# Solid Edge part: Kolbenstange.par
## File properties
Username: bmolnar
Dokumentum tartalom típus: 0
Author: bmolnar
Last saved by: bmolnar
Revision: 82
Sűrűség: 0,000 kg/m^3
Pontosság: 0,990
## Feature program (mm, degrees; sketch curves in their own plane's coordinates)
base feature "unnamed BaseFeature 1"
sketch for "unnamed Protrusion 1" plane through (-0.0012, 0, -18.75) normal (0, 0, -1) x-axis (0, -1, 0)
  circle centre (0, -0.0012) radius 25
extrude "unnamed Protrusion 1" add finite 8.3 along +normal
sketch for "Kihúzás_2" #1 plane through (-0.0012, 0, -18.75) normal (0, 0, -1) x-axis (0, -1, 0)
  circle centre (0, -0.0012) radius 8
sketch for "Kihúzás_2" #2 plane through (-0.0012, 0, -18.75) normal (0, 0, -1) x-axis (0, -1, 0)
  circle centre (0, -0.0012) radius 25
extrude "Kihúzás_2" add finite 18.8 along -normal
sketch for "Furat_1" plane through (0, 0, 31.0163) normal (0, 0, 1) x-axis (0, 1, 0)
  hole centre (0, 0) bore radius 3.3235
hole "Furat_1" nominal diameter 8 finite  VBottomAngle = 118 deg; ThreadDepth = 14.27 mm
chamfer "Letörés_1" setback 0.7  SetBackValue2 = 45 deg
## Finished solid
Body 1: solid body, 17 faces, 23 edges, 8 vertices.
  Faces by surface: plane 8, cylinder 5, cone 3, torus 1
  Edges by curve: circle 13, line 6, curve on surface 2, ellipse 2
Bounding box of the edges (mm; curved faces can reach further): 50.000 x 50.000 x 60.800, from (-25, -25, -27.05) to (25, 25, 33.75).
Cylindrical faces by radius (mm): R3.3235 x2, R4.125 x1, R8 x1, R25 x1
Conical faces (half-angle, radius in mm at the cone's reference point): 45 deg R4.0235 x1, 45 deg R4.225 x1, 59 deg R3.3235 x1
Toroidal faces (ring radius, tube radius in mm): R6.2 r1.8 x1
Planar faces by outward normal: +x 1, +z 3, -x 1, -z 1, oblique 2
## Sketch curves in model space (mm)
circle centre (0, 0, -18.75) radius 8
circle centre (0, 0, -18.75) radius 25
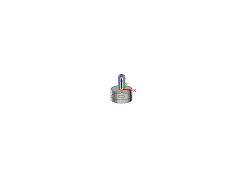
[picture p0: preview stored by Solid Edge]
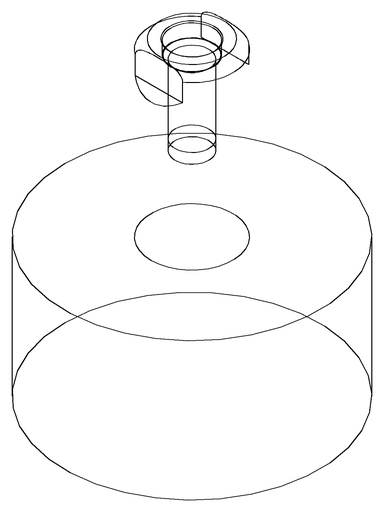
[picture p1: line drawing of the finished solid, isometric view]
